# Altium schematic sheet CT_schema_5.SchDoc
size 312 x 277 mm
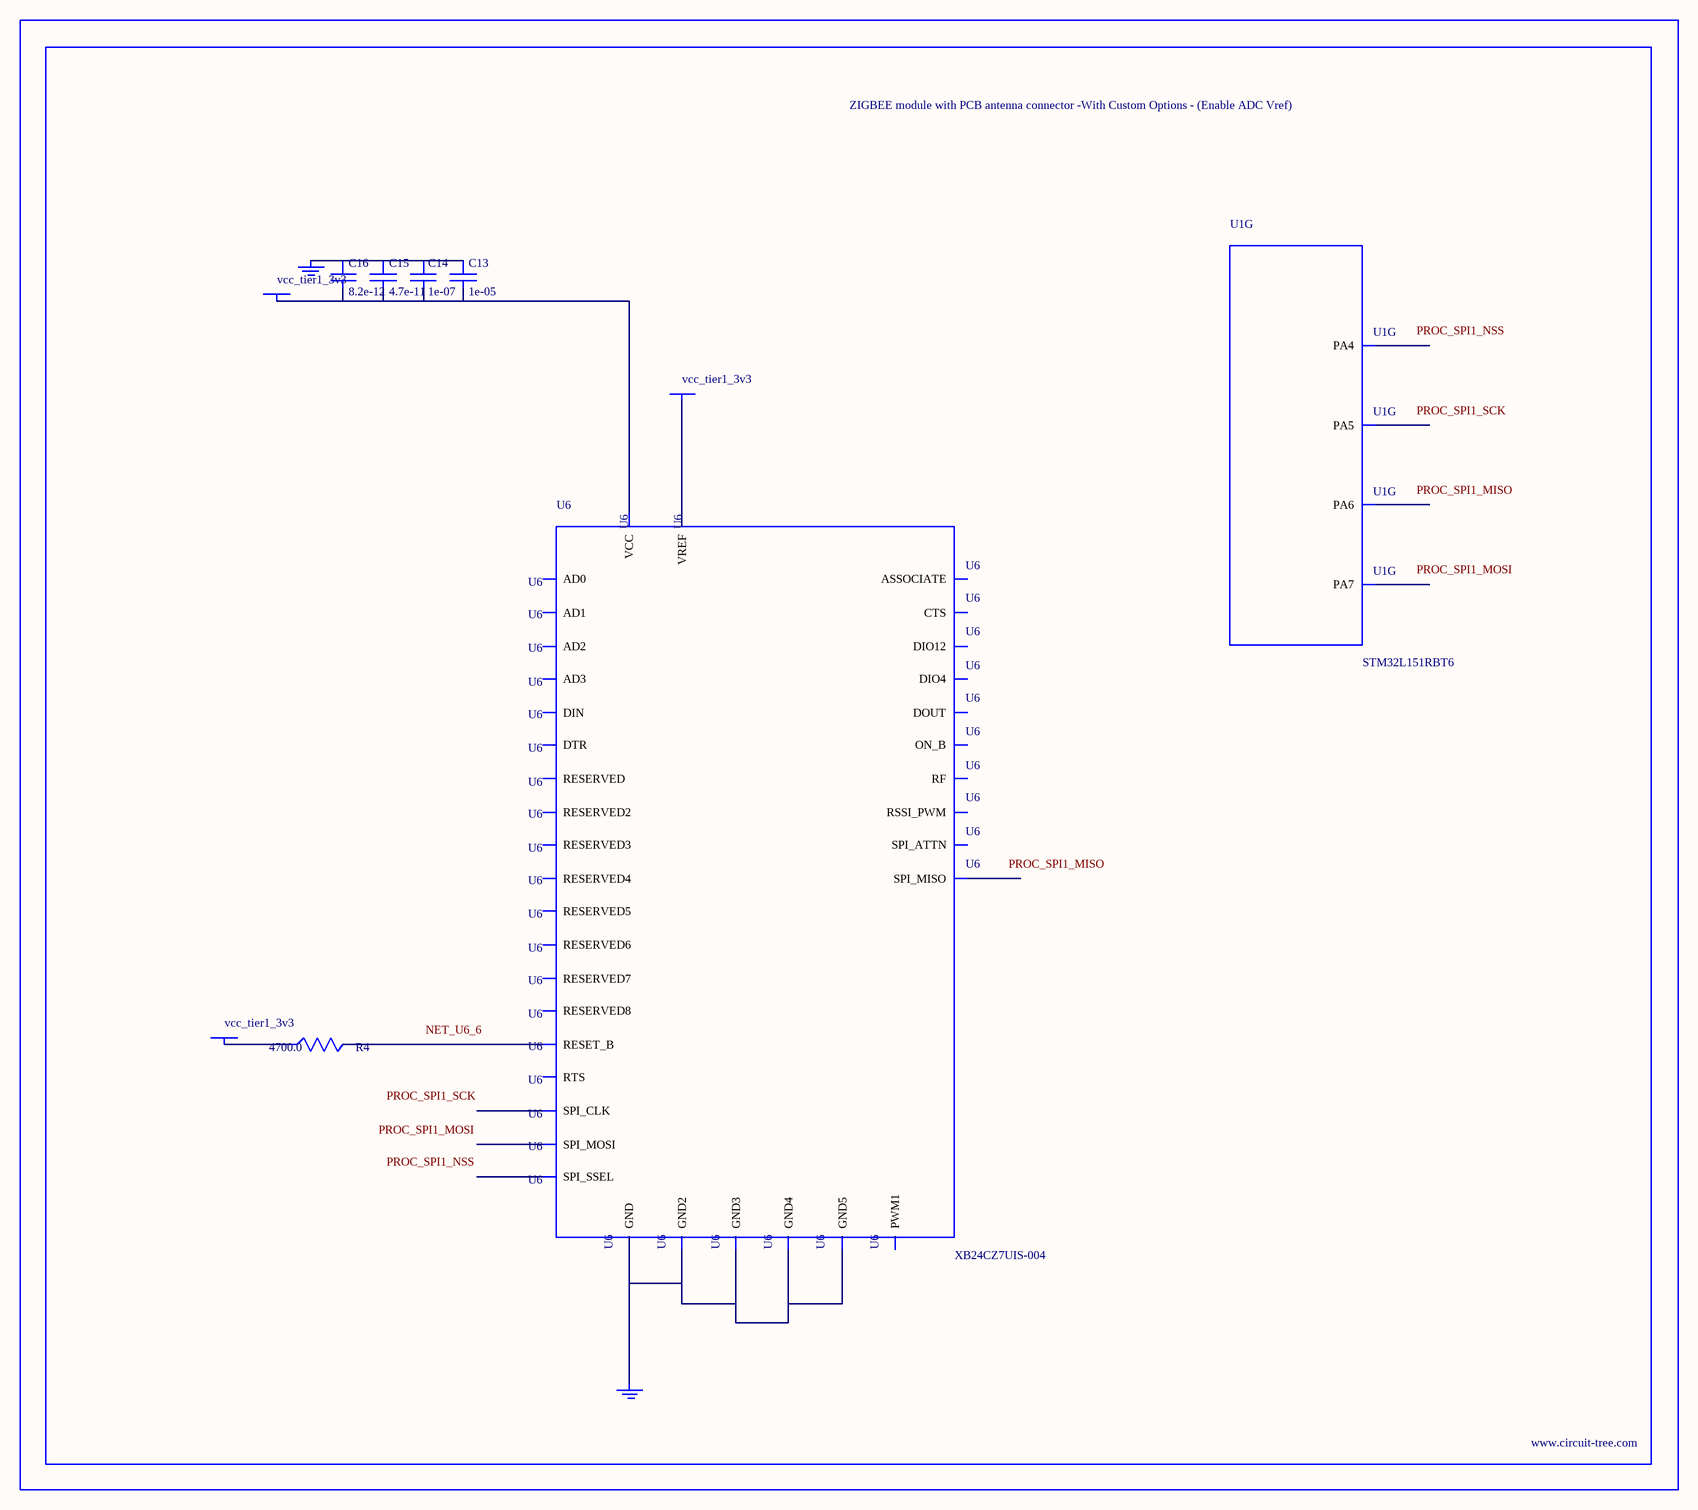
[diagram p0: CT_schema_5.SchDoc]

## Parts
BORDER4  (no value)
C13  1e-05  [C0805]
C14  1e-07  [C0402]
C15  4.7e-11  [C0402]
C16  8.2e-12  [C0603]
GND_INSTANCE_4_0  (no value)
GND_INSTANCE_4_1  (no value)
POWER_INSTANCE_4_0  vcc_tier1_3v3
POWER_INSTANCE_4_1  vcc_tier1_3v3
POWER_INSTANCE_4_2  vcc_tier1_3v3
R4  4700.0  [R0603]
U1  STM32L151RBT6  [LQFP64]  (part G of 7)
U6  XB24CZ7UIS-004  [XB24CZ7UIS-004]

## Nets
NetC13_1: C13.1 C14.1 C15.1 C16.1 GND_INSTANCE_4_0.0(GND)
NetC13_2: C13.2 C14.2 C15.2 C16.2 POWER_INSTANCE_4_0.0(PWR) U6.2(VCC)
NetGND_INSTANCE_4_1_0: GND_INSTANCE_4_1.0(GND) U6.1(GND) U6.11(GND2) U6.13(GND3) U6.22(GND4) U6.35(GND5)
NetPOWER_INSTANCE_4_1_0: POWER_INSTANCE_4_1.0(PWR) R4.1
NetPOWER_INSTANCE_4_2_0: POWER_INSTANCE_4_2.0(PWR) U6.27(VREF)
NetR4_2: R4.2 U6.6(RESET_B)

Not connected (* = marked no-connect by the designer): U1 20(PA4) 21(PA5) 22(PA6) 23(PA7); U6 3(DOUT) 4(DIN) 5(DIO12) 7(RSSI_PWM) 8(PWM1) 9(RESERVED) 10(DTR) 12(SPI_ATTN) 14(SPI_CLK) 15(SPI_SSEL) 16(SPI_MOSI) 17(SPI_MISO) 18(RESERVED2) 19(RESERVED3) 20(RESERVED4) 21(RESERVED5) 23(RESERVED6) 24(DIO4) 25(CTS) 26(ON_B) 28(ASSOCIATE) 29(RTS) 30(AD3) 31(AD2) 32(AD1) 33(AD0) 34(RESERVED7) 36(RF) 37(RESERVED8)

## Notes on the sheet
- Labels drawn without touching a wire or pin: NET_U6_6, PROC_SPI1_MISO, PROC_SPI1_MOSI, PROC_SPI1_NSS, PROC_SPI1_SCK

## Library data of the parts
BORDER4 = BORDER_PAGE4
C13 = C0805C106K8RACTU
C14 = C0402C104K3RACTU
C15 = C0402C470K3RAC
C16 = 06035J8R2BBTTR
GND_INSTANCE_4_0 GND_INSTANCE_4_1 = GND
POWER_INSTANCE_4_0-POWER_INSTANCE_4_2 = PWR
R4 = RC0603JR-074K7L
